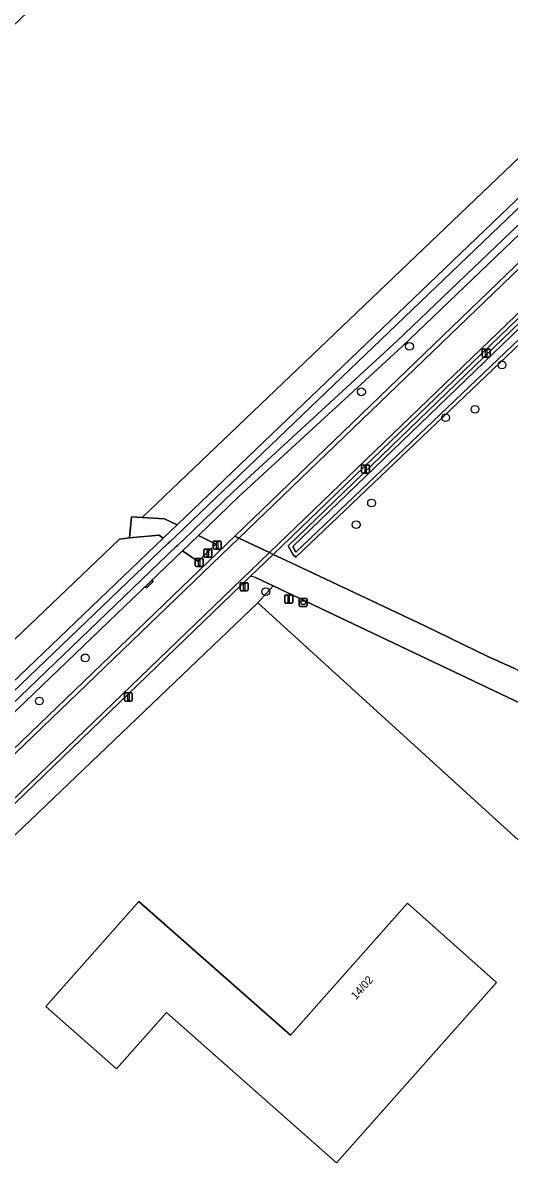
# Model space of a CAD drawing. Extents: x 157132 to 159279, y 384991 to 386650.
# Drawn here: x 157894.6 to 157955.4, y 386020.3 to 386164.9 of the extents above; entities that cross this region are included whole.
import ezdxf

# ---------------------------------------------------------------- set-up
doc = ezdxf.new("R2010")
doc.units = 0
for name, color, linetype in [('IMGEO_Afsluitpaal', 7, 'Continuous'), ('IMGEO_Afvalbak', 7, 'Continuous'), ('IMGEO_Boom', 7, 'Continuous'), ('IMGEO_Bouwland', 7, 'Continuous'), ('IMGEO_Gemengd_bos', 7, 'Continuous'), ('IMGEO_Groenvoorziening', 7, 'Continuous'), ('IMGEO_Hek', 7, 'Continuous'), ('IMGEO_Lichtmast', 7, 'Continuous'), ('IMGEO_Muur', 7, 'Continuous'), ('IMGEO_Oever', 7, 'Continuous'), ('IMGEO_Pand', 7, 'Continuous'), ('IMGEO_Pand_nummerreeks', 7, 'Continuous'), ('IMGEO_Rijbaan_lokaal_open', 7, 'Continuous'), ('IMGEO_Verkeersbordpaal', 7, 'Continuous'), ('IMGEO_Voetpad_halfverhard', 7, 'Continuous'), ('IMGEO_Waterloop', 7, 'Continuous')]:
    doc.layers.add(name, color=color, linetype=linetype)

msp = doc.modelspace()

# ---------------------------------------------------------------- linework, layer by layer
at = {"layer": 'IMGEO_Afsluitpaal'}
for p, q in [((157918.34, 386099.32), (157918.34, 386100.12)), ((157918.34, 386100.12), (157918.34, 386099.32)), ((157918.44, 386100.22), (157919.23, 386100.22)), ((157919.23, 386100.22), (157918.44, 386100.22)), ((157919.33, 386100.12), (157919.33, 386099.32)), ((157919.33, 386099.32), (157919.33, 386100.12)), ((157916.2, 386098.05), (157916.99, 386098.05)), ((157916.99, 386098.05), (157916.2, 386098.05)), ((157917.17, 386098.32), (157917.17, 386099.12)), ((157917.17, 386099.12), (157917.17, 386098.32)), ((157917.27, 386099.22), (157918.06, 386099.22)), ((157918.06, 386099.22), (157917.27, 386099.22)), ((157918.06, 386098.22), (157917.27, 386098.22)), ((157917.27, 386098.22), (157918.06, 386098.22)), ((157918.16, 386099.12), (157918.16, 386098.32)), ((157918.16, 386098.32), (157918.16, 386099.12)), ((157919.23, 386099.22), (157918.44, 386099.22)), ((157918.44, 386099.22), (157919.23, 386099.22)), ((157916.1, 386097.15), (157916.1, 386097.95)), ((157916.1, 386097.95), (157916.1, 386097.15)), ((157916.99, 386097.05), (157916.2, 386097.05)), ((157916.2, 386097.05), (157916.99, 386097.05)), ((157917.09, 386097.95), (157917.09, 386097.15)), ((157917.09, 386097.15), (157917.09, 386097.95))]:
    msp.add_line(p, q, dxfattribs=at)
for points in [[(157918.76, 386100.1), (157918.91, 386100.1), (157918.91, 386099.35), (157918.76, 386099.35), (157918.76, 386100.1)], [(157917.59, 386099.1), (157917.74, 386099.1), (157917.74, 386098.35), (157917.59, 386098.35), (157917.59, 386099.1)], [(157916.52, 386097.93), (157916.67, 386097.93), (157916.67, 386097.18), (157916.52, 386097.18), (157916.52, 386097.93)]]:
    msp.add_lwpolyline(points, dxfattribs=at)
for centre, start, end in [((157918.44, 386100.12), 90, 180), ((157918.44, 386100.12), 90, 180), ((157919.23, 386100.12), 0, 90), ((157919.23, 386100.12), 360, 90), ((157916.2, 386097.95), 90, 180), ((157916.2, 386097.95), 90, 180), ((157916.99, 386097.95), 0, 90), ((157916.99, 386097.95), 360, 90), ((157917.27, 386099.12), 90, 180), ((157917.27, 386099.12), 90, 180), ((157917.27, 386098.32), 180, 270), ((157917.27, 386098.32), 180, 270), ((157918.06, 386099.12), 0, 90), ((157918.06, 386099.12), 360, 90), ((157918.06, 386098.32), 270, 0), ((157918.06, 386098.32), 270, 0), ((157918.44, 386099.32), 180, 270), ((157918.44, 386099.32), 180, 270), ((157919.23, 386099.32), 270, 0), ((157919.23, 386099.32), 270, 0), ((157916.2, 386097.15), 180, 270), ((157916.2, 386097.15), 180, 270), ((157916.99, 386097.15), 270, 0), ((157916.99, 386097.15), 270, 0)]:
    msp.add_arc(centre, 0.1, start, end, dxfattribs=at)
at = {"layer": 'IMGEO_Afvalbak'}
for p, q in [((157929.09, 386092.15), (157929.09, 386092.95)), ((157929.09, 386092.95), (157929.09, 386092.15)), ((157929.19, 386093.05), (157929.98, 386093.05)), ((157929.98, 386093.05), (157929.19, 386093.05)), ((157930.08, 386092.95), (157930.08, 386092.15)), ((157930.08, 386092.15), (157930.08, 386092.95)), ((157929.98, 386092.05), (157929.19, 386092.05)), ((157929.19, 386092.05), (157929.98, 386092.05))]:
    msp.add_line(p, q, dxfattribs=at)
msp.add_lwpolyline([(157929.23, 386092.77), (157929.94, 386092.77), (157929.79, 386092.3), (157929.38, 386092.3), (157929.23, 386092.77)], dxfattribs=at)
for centre, start, end in [((157929.19, 386092.95), 90, 180), ((157929.19, 386092.95), 90, 180), ((157929.98, 386092.95), 0, 90), ((157929.98, 386092.95), 360, 90), ((157929.19, 386092.15), 180, 270), ((157929.19, 386092.15), 180, 270), ((157929.98, 386092.15), 270, 0), ((157929.98, 386092.15), 270, 0)]:
    msp.add_arc(centre, 0.1, start, end, dxfattribs=at)
at = {"layer": 'IMGEO_Boom'}
for centre in [(157942.86, 386124.54), (157954.43, 386122.22), (157936.86, 386118.86), (157951.05, 386116.67), (157947.39, 386115.64), (157938.13, 386104.97), (157936.21, 386102.27), (157924.92, 386093.9), (157902.35, 386085.62), (157896.61, 386080.24)]:
    msp.add_circle(centre, 0.489, dxfattribs=at)
at = {"layer": 'IMGEO_Bouwland'}
msp.add_lwpolyline([(157907.89, 386100.62), (157908.11, 386103.25), (157909.47, 386103.17), (157972.32, 386163.18), (157975.23, 386165.96), (157973.79, 386167.47), (157936.15, 386206.72), (157933.34, 386204.01), (157921.22, 386191.28), (157874.85, 386146.92), (157824.5, 386097.81), (157804.71, 386079.73), (157842.48, 386039.2), (157906.64, 386100.46)], close=True, dxfattribs=at)
at = {"layer": 'IMGEO_Gemengd_bos'}
for points in [[(158236.28, 386387.72), (158234.12, 386389.9), (158232.67, 386391.38), (158232.17, 386391.88), (158095.09, 386261.28), (158031.71, 386200.74), (157962.02, 386133.38), (157925.85, 386098.55), (157928, 386097.54), (157944.77, 386089.65), (157952.64, 386085.78), (157955.9, 386084.35)], [(158001.54, 386050.04), (158000, 386050.87), (157996.46, 386052.93), (157993.21, 386055.25), (157983.96, 386062.91), (157976.98, 386068.09), (157969.25, 386073.06), (157964.03, 386076.09), (157956.78, 386079.93), (157925.82, 386094.62), (157923.9, 386092.49), (157974.24, 386046.68), (158002.86, 386000), (158038.99, 385941.05), (158062.63, 385902.16), (158067.95, 385899.1)]]:
    msp.add_lwpolyline(points, dxfattribs=at)
msp.add_lwpolyline([(158097.81, 386259.86), (158093.55, 386255.76), (158000, 386166.56), (157984.01, 386150.94), (157928.68, 386098.19), (157928.32, 386098.49), (157927.7, 386099.61), (157983.67, 386153.58), (158044.45, 386212.41), (158091.73, 386257.09), (158096.55, 386261.77), (158127.84, 386291.56), (158191.46, 386352.38), (158230.02, 386389.09), (158231.31, 386387.22)], close=True, dxfattribs=at)
at = {"layer": 'IMGEO_Groenvoorziening'}
for points in [[(158246.36, 386438.85), (158246.84, 386432.88), (158248.77, 386427.05), (158240.43, 386419.1), (158093.72, 386279.1), (158091.16, 386276.65), (157975.23, 386165.96), (157972.32, 386163.18), (157909.47, 386103.17), (157912.27, 386103.01), (157913.82, 386102.24), (158240.57, 386415.07), (158240.69, 386415.19), (158244.91, 386419.57), (158247.69, 386422.99)], [(157841.16, 386023.24), (157840.78, 386023.62), (157877.74, 386059.18), (157921.03, 386100.83), (157958.38, 386136.76), (158006.36, 386183.22), (158048.9, 386224.14), (158243.2, 386409.3), (158244.83, 386411.77), (158245.36, 386411.41), (158254.46, 386424.63)], [(158252.27, 386422.97), (158247.48, 386416.73), (158244.19, 386412.89), (158243.62, 386413.14), (158143.52, 386317.82), (158000, 386180.76), (157977.11, 386158.17), (157941.94, 386124.54), (157921.52, 386105.73), (157916.5, 386100.92), (157918.67, 386099.84), (157916.45, 386097.68), (157914.49, 386098.99), (157875.32, 386061.42), (157837.74, 386025.65), (157836.83, 386026.59), (157836.07, 386025.87), (157838.49, 386023.17), (157839.07, 386023.03), (157840.1, 386022.98)], [(157878.48, 386049.1), (157923.9, 386092.49), (157925.82, 386094.62), (157923.61, 386095.67)], [(157923.02, 386095.83), (157879.56, 386053.99), (157879.21, 386054.36)], [(157923.9, 386092.49), (157878.48, 386049.1)], [(158062.63, 385902.16), (158038.99, 385941.05), (158002.86, 386000), (157974.24, 386046.68), (157923.9, 386092.49)]]:
    msp.add_lwpolyline(points, dxfattribs=at)
for points in [[(157836.83, 386026.59), (157835.85, 386027.6), (157873.22, 386063.38), (157912.1, 386100.6), (157911.57, 386100.96), (157907.89, 386100.62), (157906.64, 386100.46), (157842.48, 386039.2), (157834.62, 386031.7), (157835.6, 386030.67), (157834.29, 386029.42), (157833.54, 386028.71), (157836.07, 386025.87)], [(157910.71, 386095.32), (157910.85, 386095.17), (157910.04, 386094.36), (157909.89, 386094.51)], [(157933.76, 386022.54), (157912.52, 386041.35), (157906.25, 386034.28), (157897.44, 386042.09), (157909.05, 386055.2), (157928, 386038.49), (157942.6, 386054.97), (157953.75, 386045.09)]]:
    msp.add_lwpolyline(points, close=True, dxfattribs=at)
msp.add_arc((157922.28, 386091.94), 3.96, 70.3485, 79.2232, dxfattribs=at)
at = {"layer": 'IMGEO_Hek'}
for points in [[(157972.32, 386163.18), (157909.47, 386103.17)], [(157906.64, 386100.46), (157834.62, 386031.7)], [(157923.9, 386092.49), (157878.48, 386049.1)]]:
    msp.add_lwpolyline(points, dxfattribs=at)
at = {"layer": 'IMGEO_Lichtmast'}
for p, q in [((157951.96, 386123.31), (157951.96, 386124.11)), ((157951.96, 386124.11), (157951.96, 386123.31)), ((157952.06, 386124.21), (157952.85, 386124.21)), ((157952.85, 386124.21), (157952.06, 386124.21)), ((157952.95, 386124.11), (157952.95, 386123.31)), ((157952.95, 386123.31), (157952.95, 386124.11)), ((157952.85, 386123.21), (157952.06, 386123.21)), ((157952.06, 386123.21), (157952.85, 386123.21)), ((157936.89, 386108.81), (157936.89, 386109.61)), ((157936.89, 386109.61), (157936.89, 386108.81)), ((157936.99, 386109.71), (157937.78, 386109.71)), ((157937.78, 386109.71), (157936.99, 386109.71)), ((157937.88, 386109.61), (157937.88, 386108.81)), ((157937.88, 386108.81), (157937.88, 386109.61)), ((157937.78, 386108.71), (157936.99, 386108.71)), ((157936.99, 386108.71), (157937.78, 386108.71)), ((157921.71, 386094.11), (157921.71, 386094.91)), ((157921.71, 386094.91), (157921.71, 386094.11)), ((157921.81, 386095.01), (157922.6, 386095.01)), ((157922.6, 386095.01), (157921.81, 386095.01)), ((157922.6, 386094.01), (157921.81, 386094.01)), ((157921.81, 386094.01), (157922.6, 386094.01)), ((157922.7, 386094.91), (157922.7, 386094.11)), ((157922.7, 386094.11), (157922.7, 386094.91)), ((157907.25, 386080.34), (157907.25, 386081.14)), ((157907.25, 386081.14), (157907.25, 386080.34)), ((157907.35, 386081.24), (157908.13, 386081.24)), ((157908.13, 386081.24), (157907.35, 386081.24)), ((157908.23, 386081.14), (157908.23, 386080.34)), ((157908.23, 386080.34), (157908.23, 386081.14)), ((157908.13, 386080.24), (157907.35, 386080.24)), ((157907.35, 386080.24), (157908.13, 386080.24))]:
    msp.add_line(p, q, dxfattribs=at)
for points in [[(157952.38, 386124.09), (157952.53, 386124.09), (157952.53, 386123.34), (157952.38, 386123.34), (157952.38, 386124.09)], [(157937.31, 386109.58), (157937.46, 386109.58), (157937.46, 386108.83), (157937.31, 386108.83), (157937.31, 386109.58)], [(157922.13, 386094.88), (157922.28, 386094.88), (157922.28, 386094.13), (157922.13, 386094.13), (157922.13, 386094.88)], [(157907.66, 386081.11), (157907.82, 386081.11), (157907.82, 386080.36), (157907.66, 386080.36), (157907.66, 386081.11)]]:
    msp.add_lwpolyline(points, dxfattribs=at)
for centre, start, end in [((157952.06, 386124.11), 90, 180), ((157952.06, 386124.11), 90, 180), ((157952.85, 386124.11), 0, 90), ((157952.85, 386124.11), 360, 90), ((157952.06, 386123.31), 180, 270), ((157952.06, 386123.31), 180, 270), ((157952.85, 386123.31), 270, 0), ((157952.85, 386123.31), 270, 0), ((157936.99, 386109.61), 90, 180), ((157936.99, 386109.61), 90, 180), ((157937.78, 386109.61), 0, 90), ((157937.78, 386109.61), 360, 90), ((157936.99, 386108.81), 180, 270), ((157936.99, 386108.81), 180, 270), ((157937.78, 386108.81), 270, 0), ((157937.78, 386108.81), 270, 0), ((157921.81, 386094.91), 90, 180), ((157921.81, 386094.91), 90, 180), ((157921.81, 386094.11), 180, 270), ((157921.81, 386094.11), 180, 270), ((157922.6, 386094.91), 0, 90), ((157922.6, 386094.91), 360, 90), ((157922.6, 386094.11), 270, 0), ((157922.6, 386094.11), 270, 0), ((157907.35, 386081.14), 90, 180), ((157907.35, 386081.14), 90, 180), ((157908.13, 386081.14), 0, 90), ((157908.13, 386081.14), 360, 90), ((157907.35, 386080.34), 180, 270), ((157907.35, 386080.34), 180, 270), ((157908.13, 386080.34), 270, 0), ((157908.13, 386080.34), 270, 0)]:
    msp.add_arc(centre, 0.1, start, end, dxfattribs=at)
at = {"layer": 'IMGEO_Muur'}
msp.add_lwpolyline([(157910.85, 386095.17), (157910.71, 386095.32), (157909.89, 386094.51), (157910.04, 386094.36)], close=True, dxfattribs=at)
at = {"layer": 'IMGEO_Oever'}
for points in [[(158247.69, 386422.99), (158244.91, 386419.57), (158240.69, 386415.19), (158240.57, 386415.07), (157913.82, 386102.24), (157912.1, 386100.6), (157873.22, 386063.38), (157835.85, 386027.6), (157836.83, 386026.59), (157837.74, 386025.65), (157875.32, 386061.42), (157914.49, 386098.99), (157916.5, 386100.92), (157921.52, 386105.73), (157941.94, 386124.54), (157977.11, 386158.17), (158000, 386180.76), (158143.52, 386317.82), (158243.62, 386413.14), (158244.19, 386412.89), (158247.48, 386416.73), (158252.27, 386422.97)], [(158142.89, 386318.48), (157999.36, 386181.41), (157976.47, 386158.82), (157941.32, 386125.21), (157920.89, 386106.4), (157915.86, 386101.58), (157915.63, 386101.35), (157913.86, 386099.65), (157913.72, 386099.52), (157874.69, 386062.08), (157837.76, 386026.94), (157837.48, 386027.22), (157837.14, 386027.57), (157873.85, 386062.72), (157912.73, 386099.94), (157912.88, 386100.08), (157914.45, 386101.59), (157914.69, 386101.81), (158241.2, 386414.41)]]:
    msp.add_lwpolyline(points, dxfattribs=at)
for points in [[(158093.55, 386255.76), (158097.81, 386259.86), (158231.31, 386387.22), (158230.02, 386389.09), (158191.46, 386352.38), (158127.84, 386291.56), (158096.55, 386261.77), (158091.73, 386257.09), (158044.45, 386212.41), (157983.67, 386153.58), (157927.7, 386099.61), (157928.32, 386098.49), (157928.68, 386098.19), (157984.01, 386150.94), (158000, 386166.56)], [(158230.69, 386387.29), (158208.35, 386366), (158182.5, 386341.31), (158097.48, 386260.21), (158093.21, 386256.1), (157999.67, 386166.91), (157983.68, 386151.28), (157928.67, 386098.85), (157928.3, 386099.52), (157984, 386153.23), (158044.78, 386212.06), (158092.05, 386256.74), (158096.89, 386261.42), (158128.17, 386291.21), (158191.79, 386352.03), (158229.95, 386388.36)]]:
    msp.add_lwpolyline(points, close=True, dxfattribs=at)
at = {"layer": 'IMGEO_Pand'}
msp.add_lwpolyline([(157933.76, 386022.54), (157953.75, 386045.09), (157942.6, 386054.97), (157928, 386038.49), (157909.05, 386055.2), (157897.44, 386042.09), (157906.25, 386034.28), (157912.52, 386041.35)], close=True, dxfattribs=at)
at = {"layer": 'IMGEO_Rijbaan_lokaal_open'}
for points in [[(158243.56, 386408.93), (158243.2, 386409.3), (158048.9, 386224.14), (158006.36, 386183.22), (157958.38, 386136.76), (157921.03, 386100.83), (157921.53, 386100.59), (157958.93, 386136.57), (158028.52, 386203.87), (158093.89, 386266.32)], [(158009.22, 386179.77), (158051.51, 386220.37), (158095.43, 386262.32), (158246.39, 386406.09), (158243.56, 386408.93), (158093.89, 386266.32), (158028.52, 386203.87), (157958.93, 386136.57), (157921.53, 386100.59), (157925.37, 386098.78), (157961.67, 386133.7)], [(158031.71, 386200.74), (158095.09, 386261.28), (158232.17, 386391.88), (158235.02, 386394.6), (158246.73, 386405.75), (158246.39, 386406.09), (158095.43, 386262.32), (158051.51, 386220.37), (158009.22, 386179.77), (157961.67, 386133.7), (157925.37, 386098.78), (157925.85, 386098.55), (157962.02, 386133.38)], [(157921.53, 386100.59), (157921.03, 386100.83), (157877.74, 386059.18), (157840.78, 386023.62), (157841.16, 386023.24)], [(157923.02, 386095.83), (157925.85, 386098.55), (157925.37, 386098.78), (157879.21, 386054.36), (157879.56, 386053.99)]]:
    msp.add_lwpolyline(points, close=True, dxfattribs=at)
for points in [[(157925.37, 386098.78), (157921.53, 386100.59), (157841.16, 386023.24)], [(157879.21, 386054.36), (157925.37, 386098.78)]]:
    msp.add_lwpolyline(points, dxfattribs=at)
at = {"layer": 'IMGEO_Verkeersbordpaal'}
for p, q in [((157927.28, 386092.58), (157927.28, 386093.37)), ((157927.28, 386093.37), (157927.28, 386092.58)), ((157927.38, 386093.47), (157928.17, 386093.47)), ((157928.17, 386093.47), (157927.38, 386093.47)), ((157928.17, 386092.48), (157927.38, 386092.48)), ((157927.38, 386092.48), (157928.17, 386092.48)), ((157928.27, 386093.37), (157928.27, 386092.58)), ((157928.27, 386092.58), (157928.27, 386093.37))]:
    msp.add_line(p, q, dxfattribs=at)
msp.add_lwpolyline([(157927.7, 386093.35), (157927.85, 386093.35), (157927.85, 386092.6), (157927.7, 386092.6), (157927.7, 386093.35)], dxfattribs=at)
for centre, start, end in [((157927.38, 386093.37), 90, 180), ((157927.38, 386093.37), 90, 180), ((157927.38, 386092.58), 180, 270), ((157927.38, 386092.58), 180, 270), ((157928.17, 386093.37), 0, 90), ((157928.17, 386093.37), 360, 90), ((157928.17, 386092.58), 270, 0), ((157928.17, 386092.58), 270, 0)]:
    msp.add_arc(centre, 0.1, start, end, dxfattribs=at)
at = {"layer": 'IMGEO_Voetpad_halfverhard'}
for points in [[(157912.1, 386100.6), (157913.82, 386102.24), (157912.27, 386103.01), (157909.47, 386103.17), (157908.11, 386103.25), (157907.89, 386100.62), (157911.57, 386100.96)], [(157916.5, 386100.92), (157914.49, 386098.99), (157916.45, 386097.68), (157918.67, 386099.84)]]:
    msp.add_lwpolyline(points, close=True, dxfattribs=at)
for points in [[(157990.35, 386062.19), (157981.31, 386070.02), (157974.67, 386074.48), (157955.9, 386084.35), (157952.64, 386085.78), (157944.77, 386089.65), (157928, 386097.54), (157925.85, 386098.55), (157923.02, 386095.83)], [(157923.61, 386095.67), (157925.82, 386094.62), (157956.78, 386079.93), (157964.03, 386076.09), (157969.25, 386073.06), (157976.98, 386068.09), (157983.96, 386062.91), (157993.21, 386055.25), (157996.46, 386052.93), (158000, 386050.87), (158001.54, 386050.04)]]:
    msp.add_lwpolyline(points, dxfattribs=at)
msp.add_arc((157922.28, 386091.94), 3.96, 70.3485, 79.2232, dxfattribs=at)
at = {"layer": 'IMGEO_Waterloop'}
msp.add_lwpolyline([(158241.2, 386414.41), (157914.69, 386101.81), (157914.45, 386101.59), (157912.88, 386100.08), (157912.73, 386099.94), (157873.85, 386062.72), (157837.14, 386027.57), (157837.48, 386027.22), (157837.76, 386026.94), (157874.69, 386062.08), (157913.72, 386099.52), (157913.86, 386099.65), (157915.63, 386101.35), (157915.86, 386101.58), (157920.89, 386106.4), (157941.32, 386125.21), (157976.47, 386158.82), (157999.36, 386181.41), (158142.89, 386318.48)], dxfattribs=at)
msp.add_lwpolyline([(158230.69, 386387.29), (158229.95, 386388.36), (158191.79, 386352.03), (158128.17, 386291.21), (158096.89, 386261.42), (158092.05, 386256.74), (158044.78, 386212.06), (157984, 386153.23), (157928.3, 386099.52), (157928.67, 386098.85), (157983.68, 386151.28), (157999.67, 386166.91), (158093.21, 386256.1), (158097.48, 386260.21), (158182.5, 386341.31), (158208.35, 386366)], close=True, dxfattribs=at)

# ---------------------------------------------------------------- texts
at = {"layer": 'IMGEO_Pand_nummerreeks'}
msp.add_text('14/02', height=1, rotation=48.1817, dxfattribs=at).set_placement((157936.18, 386042.86))

doc.saveas('drawing.dxf')
